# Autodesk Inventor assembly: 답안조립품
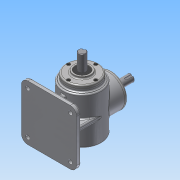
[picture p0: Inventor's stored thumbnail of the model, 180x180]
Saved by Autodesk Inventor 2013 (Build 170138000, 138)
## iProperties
Created: 2015-07
Part Number: 답안조립품
Document SubType Name: Assembly
Designer: Administrator
Author: Administrator
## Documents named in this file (14)
- C:\Users\Administrator\Desktop\450706V1023\답안조립품.iam
- C:\Users\Administrator\Desktop\450706V1023\본체.ipt
- C:\Users\Administrator\Desktop\450706V1023\M4.ipt
- C:\Users\Administrator\Desktop\450706V1023\메인 베벨기어.ipt
- C:\Users\Administrator\Desktop\450706V1023\메인 축.ipt
- 메인 축.ipt
- C:\Users\Administrator\Desktop\450706V1023\베어링 6203.ipt
- C:\Users\Administrator\Desktop\450706V1023\서브 베벨기어.ipt
- C:\Users\Administrator\Desktop\450706V1023\서브 축.ipt
- 서브 축.ipt
- C:\Users\Administrator\Desktop\450706V1023\오일실.ipt
- C:\Users\Administrator\Desktop\450706V1023\커버.ipt
- C:\Users\Administrator\Desktop\450706V1023\키 4x4.ipt
- C:\Users\Administrator\Desktop\450706V1023\키 5x5.ipt
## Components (8 placed, 1 different names)
1. M4:1
2. M4:2
3. M4:3
4. M4:4
5. M4:5
6. M4:6
7. M4:7
8. M4:8
